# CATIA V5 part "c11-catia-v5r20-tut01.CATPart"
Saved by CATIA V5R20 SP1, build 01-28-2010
Part number: c11tut1
Bounding box of the stored display mesh (mm): x -74.368 to 0, y -50 to 50, z -100 to 0
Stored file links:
  D:\v5_r20\psrt_files_downloaded\c11\c11-catia-v5r20-tut01.CATPart
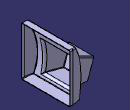
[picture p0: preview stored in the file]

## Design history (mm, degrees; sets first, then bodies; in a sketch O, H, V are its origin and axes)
Body1 (main body)
  Sketch1 on zx-plane, origin (0, 0, 0), H (-1, 0, 0), V (0, 0, 1)
    line L1 (0, 0) -> (12, 0)
    line L2 (0, -100) -> (22, -100)
    point P2 (0, -100)
    arc A1 centre (-96.8872, -61.3887) radius 125 from (12, 0) to (22, -100) cw
    length L1 = 12
    length L2 = 22
    radius A1 = 125
    distance L2 L1 = 100
    horizontal: L1 H, L2 H
    coincidence: P2 V
  Extrude1: Element1 Sketch1, Lim1 50, Lim2 50, Direction zx-plane
  Sketch2 on zx-plane, origin (0, 0, 0), H (-1, 0, 0), V (0, 0, 1)
    line L1 (20, -40) -> (74.9495, -60)
    point P1 (20, -40)
    point P2 (74.9495, -60)
    reference projected line E1 (22, -100) -> (0, -100) from edge of Extrude1
    angle L1 H = 20
    distance P1 V = 20
    distance E1 P1 = 60
    distance H P2 = 60
  Plane1: type Normal, Curve Sketch2, RefPoint Sketch2.P2
  Sketch3 on Plane1, origin (-85.4657, 0, -31.107), H (0, -1, 0), V (-0.342, 0, 0.9397)
    line L1 (-25, -30.7473) -> (25, -30.7473)
    line L2 (25, -30.7473) -> (25, -70.7473)
    line L3 (25, -70.7473) -> (-25, -70.7473)
    line L4 (-25, -70.7473) -> (-25, -30.7473)
    reference projected point E1 (0, -30.7473) from Sketch2.P2
    reference projected point E2 (0, -30.7473) from Sketch2.P2
    length L2 = 40
    length L3 = 50
    distance L4 E2 = 25
    horizontal: L1 H, L3 H
    vertical: L2 V, L4 V
    coincidence: E1 L1
  Plane2: type Normal, Curve Sketch2, RefPoint Sketch2.P1
  Sketch4 on Plane2, origin (-30.5162, 0, -11.107), H (0, -1, 0), V (-0.342, 0, 0.9397)
    line L1 (-32.5, -21.2473) -> (32.5, -21.2473)
    line L2 (32.5, -21.2473) -> (32.5, -81.2473)
    line L3 (32.5, -81.2473) -> (-32.5, -81.2473)
    line L4 (-32.5, -81.2473) -> (-32.5, -21.2473)
    reference projected line E1 (25, -30.7473) -> (-25, -30.7473) from Sketch3.L1
    distance E1 L1 = 9.5
    length L2 = 60
    distance L4 L2 = 65
    distance V L2 = 32.5
    horizontal: L1 H, L3 H
    vertical: L2 V, L4 V
  Loft1: Sections (Sketch4; Sketch3)
  Sketch5 on face of Extrude1 from Sketch1.L1, origin (0, 0, 0), H (1, 0, 0), V (0, -1, 0)
    line L1 (-5, -50) -> (0, -50)
    point P2 (0, -50)
    arc A1 centre (-5, 0) radius 50 from (-29.6886, -43.4796) to (-5, -50) ccw
    reference projected line E1 (0, -50) -> (0, 50) from edge of Extrude1
    reference projected line E2 (-22, -50) -> (0, -50) from edge of Extrude1
    length L1 = 5
    radius A1 = 50
    horizontal: L1 H
    tangency: A1 L1
    coincidence: P2 E1, L1 E2
  Extrude2: Element1 Sketch5, Lim1 100, Lim2 0
  Symmetry1: ToTransfor Extrude2, Reference zx-plane
  Trim1: Trimmed (Extrude2; Extrude1)
  Trim2: Trimmed (Symmetry1; Trim1)
  Trim3: Trimmed (Trim2; Loft1)
  CloseSurface1: CloseElement Trim3
  Sketch6 on face of CloseSurface1, origin (-85.4657, 0, -31.107), H (0, -1, 0), V (-0.342, 0, 0.9397)
    line L1 (-20, -55.7473) -> (0, -55.7473)
    line L2 (0, -55.7473) -> (0, -65.7473)
    line L3 (0, -65.7473) -> (-20, -65.7473)
    line L4 (-20, -65.7473) -> (-20, -55.7473)
    reference projected line E1 (-25, -70.7473) -> (25, -70.7473) from edge [face of CloseSurface1 | face of CloseSurface1]
    reference projected line E2 (-25, -30.7473) -> (-25, -70.7473) from edge [face of CloseSurface1 | face of CloseSurface1]
    length L1 = 20
    length L4 = 10
    distance E1 L3 = 5
    distance L4 E2 = 5
    horizontal: L1 H, L3 H
    vertical: L2 V, L4 V
  Pocket1: profile Sketch6, direction (0.9397, 0, 0.342), length 5
  Fillet1: radius 1, on end face of Pocket1; edge [face of Pocket1 from Sketch6.L1 | face of Pocket1 from Sketch6.L2]; edge [face of Pocket1 from Sketch6.L4 | face of Pocket1 from Sketch6.L1]; edge [face of Pocket1 from Sketch6.L2 | face of Pocket1 from Sketch6.L3]; edge [face of Pocket1 from Sketch6.L3 | face of Pocket1 from Sketch6.L4]
  Fillet2: radius 3.5, on edge [face of CloseSurface1 | face of CloseSurface1] (x4)
  Fillet3: radius 2, on face of CloseSurface1; edge [face of CloseSurface1 | face of CloseSurface1] (x4)
  Shell1: IntOffset 1, Face face of CloseSurface1, ExtOffset 0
